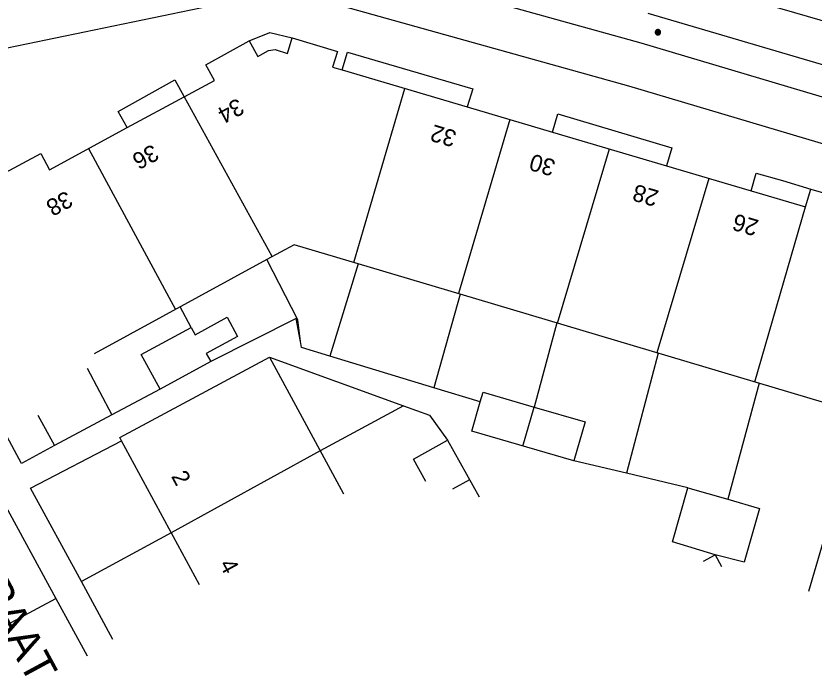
# Model space of a CAD drawing. Extents: x 81065 to 81486, y 452384 to 452681.
# Drawn here: x 81293.93 to 81331.82, y 452479.86 to 452511.24 of the extents above; entities that cross this region are included whole.
import ezdxf

# ---------------------------------------------------------------- set-up
doc = ezdxf.new("R2010")
doc.units = 0
for name, color, linetype in [('B-BH-AL-TOPOGRAFIE_HUISNUMMER-T25', 7, 'Continuous'), ('B-BH-AL-TOPOGRAFIE_STRAATNAAM-S', 7, 'Continuous'), ('B-BH-GR-BOOM-S', 7, 'Continuous'), ('B-BH-OG-TERREIN_ERF-GV', 7, 'Continuous'), ('B-BH-OG-TOPOGRAFIE_BEBOUWING-GV', 7, 'Continuous'), ('B-BH-OG-TOPOGRAFIE_BEBOUWING_PANDSCHEIDING-GV', 7, 'Continuous'), ('B-BH-VH-KANTOPSLUITING-GV', 7, 'Continuous')]:
    doc.layers.add(name, color=color, linetype=linetype)

msp = doc.modelspace()

# ---------------------------------------------------------------- linework, layer by layer
at = {"layer": 'B-BH-GR-BOOM-S'}
for points in [[(81324.281, 452510.463), (81324.282, 452510.449), (81324.284, 452510.436), (81324.288, 452510.423), (81324.292, 452510.41), (81324.299, 452510.398), (81324.306, 452510.387), (81324.314, 452510.377), (81324.324, 452510.367), (81324.334, 452510.359), (81324.346, 452510.351), (81324.358, 452510.345), (81324.37, 452510.34), (81324.383, 452510.337), (81324.397, 452510.335), (81324.41, 452510.334), (81324.424, 452510.335), (81324.437, 452510.337), (81324.45, 452510.34), (81324.463, 452510.345), (81324.475, 452510.351), (81324.486, 452510.359), (81324.496, 452510.367), (81324.506, 452510.377), (81324.515, 452510.387), (81324.522, 452510.398), (81324.528, 452510.41), (81324.533, 452510.423), (81324.536, 452510.436), (81324.538, 452510.449), (81324.539, 452510.463), (81324.538, 452510.476), (81324.536, 452510.49), (81324.533, 452510.503), (81324.528, 452510.515), (81324.522, 452510.527), (81324.515, 452510.539), (81324.506, 452510.549), (81324.496, 452510.559), (81324.486, 452510.567), (81324.475, 452510.575), (81324.463, 452510.581), (81324.45, 452510.585), (81324.437, 452510.589), (81324.424, 452510.591), (81324.41, 452510.592), (81324.397, 452510.591), (81324.383, 452510.589), (81324.37, 452510.585), (81324.358, 452510.581), (81324.346, 452510.575), (81324.334, 452510.567), (81324.324, 452510.559), (81324.314, 452510.549), (81324.306, 452510.539), (81324.299, 452510.527), (81324.292, 452510.515), (81324.288, 452510.503), (81324.284, 452510.49), (81324.282, 452510.476), (81324.281, 452510.463)], [(81324.306, 452510.463), (81324.306, 452510.452), (81324.308, 452510.441), (81324.311, 452510.431), (81324.315, 452510.42), (81324.32, 452510.411), (81324.326, 452510.402), (81324.333, 452510.393), (81324.34, 452510.385), (81324.349, 452510.378), (81324.358, 452510.372), (81324.368, 452510.367), (81324.378, 452510.364), (81324.389, 452510.361), (81324.399, 452510.359), (81324.41, 452510.358), (81324.421, 452510.359), (81324.432, 452510.361), (81324.443, 452510.364), (81324.453, 452510.367), (81324.462, 452510.372), (81324.472, 452510.378), (81324.48, 452510.385), (81324.488, 452510.393), (81324.495, 452510.402), (81324.501, 452510.411), (81324.506, 452510.42), (81324.51, 452510.431), (81324.512, 452510.441), (81324.514, 452510.452), (81324.515, 452510.463), (81324.514, 452510.474), (81324.512, 452510.485), (81324.51, 452510.495), (81324.506, 452510.505), (81324.501, 452510.515), (81324.495, 452510.524), (81324.488, 452510.533), (81324.48, 452510.54), (81324.472, 452510.547), (81324.462, 452510.553), (81324.453, 452510.558), (81324.443, 452510.562), (81324.432, 452510.565), (81324.421, 452510.567), (81324.41, 452510.567), (81324.399, 452510.567), (81324.389, 452510.565), (81324.378, 452510.562), (81324.368, 452510.558), (81324.358, 452510.553), (81324.349, 452510.547), (81324.34, 452510.54), (81324.333, 452510.533), (81324.326, 452510.524), (81324.32, 452510.515), (81324.315, 452510.505), (81324.311, 452510.495), (81324.308, 452510.485), (81324.306, 452510.474), (81324.306, 452510.463)], [(81324.329, 452510.463), (81324.329, 452510.454), (81324.33, 452510.446), (81324.333, 452510.438), (81324.336, 452510.43), (81324.34, 452510.422), (81324.344, 452510.415), (81324.35, 452510.408), (81324.356, 452510.402), (81324.362, 452510.397), (81324.369, 452510.392), (81324.377, 452510.388), (81324.385, 452510.385), (81324.393, 452510.383), (81324.402, 452510.382), (81324.41, 452510.381), (81324.419, 452510.382), (81324.427, 452510.383), (81324.435, 452510.385), (81324.443, 452510.388), (81324.451, 452510.392), (81324.458, 452510.397), (81324.465, 452510.402), (81324.471, 452510.408), (81324.476, 452510.415), (81324.481, 452510.422), (81324.485, 452510.43), (81324.488, 452510.438), (81324.49, 452510.446), (81324.491, 452510.454), (81324.492, 452510.463), (81324.491, 452510.471), (81324.49, 452510.48), (81324.488, 452510.488), (81324.485, 452510.496), (81324.481, 452510.504), (81324.476, 452510.511), (81324.471, 452510.518), (81324.465, 452510.523), (81324.458, 452510.529), (81324.451, 452510.533), (81324.443, 452510.537), (81324.435, 452510.54), (81324.427, 452510.543), (81324.419, 452510.544), (81324.41, 452510.544), (81324.402, 452510.544), (81324.393, 452510.543), (81324.385, 452510.54), (81324.377, 452510.537), (81324.369, 452510.533), (81324.362, 452510.529), (81324.356, 452510.523), (81324.35, 452510.518), (81324.344, 452510.511), (81324.34, 452510.504), (81324.336, 452510.496), (81324.333, 452510.488), (81324.33, 452510.48), (81324.329, 452510.471), (81324.329, 452510.463)], [(81324.352, 452510.463), (81324.352, 452510.457), (81324.353, 452510.451), (81324.354, 452510.445), (81324.357, 452510.439), (81324.359, 452510.434), (81324.363, 452510.428), (81324.367, 452510.424), (81324.371, 452510.419), (81324.376, 452510.415), (81324.381, 452510.412), (81324.386, 452510.409), (81324.392, 452510.407), (81324.398, 452510.405), (81324.404, 452510.404), (81324.41, 452510.404), (81324.416, 452510.404), (81324.422, 452510.405), (81324.428, 452510.407), (81324.434, 452510.409), (81324.44, 452510.412), (81324.445, 452510.415), (81324.449, 452510.419), (81324.454, 452510.424), (81324.458, 452510.428), (81324.461, 452510.434), (81324.464, 452510.439), (81324.466, 452510.445), (81324.468, 452510.451), (81324.469, 452510.457), (81324.469, 452510.463), (81324.469, 452510.469), (81324.468, 452510.475), (81324.466, 452510.481), (81324.464, 452510.487), (81324.461, 452510.492), (81324.458, 452510.497), (81324.454, 452510.502), (81324.449, 452510.507), (81324.445, 452510.51), (81324.44, 452510.514), (81324.434, 452510.517), (81324.428, 452510.519), (81324.422, 452510.52), (81324.416, 452510.521), (81324.41, 452510.522), (81324.404, 452510.521), (81324.398, 452510.52), (81324.392, 452510.519), (81324.386, 452510.517), (81324.381, 452510.514), (81324.376, 452510.51), (81324.371, 452510.507), (81324.367, 452510.502), (81324.363, 452510.497), (81324.359, 452510.492), (81324.357, 452510.487), (81324.354, 452510.481), (81324.353, 452510.475), (81324.352, 452510.469), (81324.352, 452510.463)], [(81324.374, 452510.463), (81324.375, 452510.459), (81324.375, 452510.455), (81324.376, 452510.452), (81324.378, 452510.448), (81324.379, 452510.445), (81324.381, 452510.442), (81324.384, 452510.439), (81324.386, 452510.436), (81324.389, 452510.434), (81324.392, 452510.432), (81324.396, 452510.43), (81324.399, 452510.429), (81324.403, 452510.428), (81324.407, 452510.427), (81324.41, 452510.427), (81324.414, 452510.427), (81324.418, 452510.428), (81324.421, 452510.429), (81324.425, 452510.43), (81324.428, 452510.432), (81324.431, 452510.434), (81324.434, 452510.436), (81324.437, 452510.439), (81324.439, 452510.442), (81324.441, 452510.445), (81324.443, 452510.448), (81324.444, 452510.452), (81324.445, 452510.455), (81324.446, 452510.459), (81324.446, 452510.463), (81324.446, 452510.467), (81324.445, 452510.47), (81324.444, 452510.474), (81324.443, 452510.477), (81324.441, 452510.481), (81324.439, 452510.484), (81324.437, 452510.487), (81324.434, 452510.489), (81324.431, 452510.492), (81324.428, 452510.494), (81324.425, 452510.496), (81324.421, 452510.497), (81324.418, 452510.498), (81324.414, 452510.498), (81324.41, 452510.499), (81324.407, 452510.498), (81324.403, 452510.498), (81324.399, 452510.497), (81324.396, 452510.496), (81324.392, 452510.494), (81324.389, 452510.492), (81324.386, 452510.489), (81324.384, 452510.487), (81324.381, 452510.484), (81324.379, 452510.481), (81324.378, 452510.477), (81324.376, 452510.474), (81324.375, 452510.47), (81324.375, 452510.467), (81324.374, 452510.463)], [(81324.397, 452510.463), (81324.397, 452510.461), (81324.398, 452510.46), (81324.398, 452510.459), (81324.398, 452510.458), (81324.399, 452510.456), (81324.4, 452510.455), (81324.401, 452510.454), (81324.402, 452510.453), (81324.403, 452510.452), (81324.404, 452510.452), (81324.405, 452510.451), (81324.406, 452510.451), (81324.408, 452510.45), (81324.409, 452510.45), (81324.41, 452510.45), (81324.412, 452510.45), (81324.413, 452510.45), (81324.414, 452510.451), (81324.415, 452510.451), (81324.417, 452510.452), (81324.418, 452510.452), (81324.419, 452510.453), (81324.42, 452510.454), (81324.421, 452510.455), (81324.421, 452510.456), (81324.422, 452510.458), (81324.423, 452510.459), (81324.423, 452510.46), (81324.423, 452510.461), (81324.423, 452510.463), (81324.423, 452510.464), (81324.423, 452510.466), (81324.423, 452510.467), (81324.422, 452510.468), (81324.421, 452510.469), (81324.421, 452510.471), (81324.42, 452510.471), (81324.419, 452510.472), (81324.418, 452510.473), (81324.417, 452510.474), (81324.415, 452510.475), (81324.414, 452510.475), (81324.413, 452510.476), (81324.412, 452510.476), (81324.41, 452510.476), (81324.409, 452510.476), (81324.408, 452510.476), (81324.406, 452510.475), (81324.405, 452510.475), (81324.404, 452510.474), (81324.403, 452510.473), (81324.402, 452510.472), (81324.401, 452510.471), (81324.4, 452510.471), (81324.399, 452510.469), (81324.398, 452510.468), (81324.398, 452510.467), (81324.398, 452510.466), (81324.397, 452510.464), (81324.397, 452510.463)]]:
    msp.add_lwpolyline(points, dxfattribs=at)
at = {"layer": 'B-BH-OG-TERREIN_ERF-GV'}
for p, q in [((81310.179, 452499.459), (81308.835, 452495.072)), ((81315.022, 452498.014), (81313.775, 452493.566)), ((81302.241, 452496.437), (81301.716, 452497.41)), ((81319.612, 452496.645), (81318.53, 452492.651)), ((81324.427, 452495.209), (81322.911, 452489.5)), ((81297.305, 452494.492), (81298.486, 452492.279)), ((81329.223, 452493.779), (81327.725, 452488.266)), ((81312.336, 452492.708), (81308.379, 452490.562)), ((81301.302, 452486.677), (81297.035, 452484.354))]:
    msp.add_line(p, q, dxfattribs=at)
msp.add_lwpolyline([(81307.43, 452495.761), (81307.306, 452496.79), (81305.843, 452499.661)], dxfattribs=at)
at = {"layer": 'B-BH-OG-TOPOGRAFIE_BEBOUWING-GV'}
for p, q in [((81309.422, 452508.675), (81315.358, 452506.916)), ((81299.207, 452505.932), (81301.913, 452507.4)), ((81315.358, 452506.916), (81319.411, 452505.716)), ((81319.411, 452505.716), (81324.811, 452504.117)), ((81324.811, 452504.117), (81328.838, 452502.923)), ((81331.67, 452503.013), (81336.689, 452501.516)), ((81303.178, 452494.808), (81300.775, 452493.495)), ((81305.973, 452495.015), (81309.477, 452488.531)), ((81314.416, 452491.075), (81315.92, 452488.38)), ((81325.836, 452488.803), (81327.725, 452488.266)), ((81327.133, 452485.628), (81327.437, 452485.072))]:
    msp.add_line(p, q, dxfattribs=at)
for points in [[(81301.913, 452507.4), (81303.346, 452508.178), (81302.936, 452508.923), (81305.007, 452510.063)], [(81305.007, 452510.063), (81305.417, 452509.318), (81305.919, 452509.595), (81306.231, 452509.649), (81306.82, 452509.458), (81307.043, 452510.206)], [(81307.043, 452510.206), (81309.193, 452509.557), (81308.964, 452508.811), (81309.422, 452508.675)], [(81295.749, 452490.824), (81294.191, 452489.974), (81292.702, 452492.703), (81292.52, 452492.606), (81289.503, 452498.156), (81288.453, 452500.086), (81290.406, 452501.174), (81289.998, 452501.96), (81295.103, 452504.706), (81295.52, 452503.931), (81299.207, 452505.932)], [(81328.838, 452502.923), (81331.416, 452502.16), (81331.67, 452503.013)], [(81334.029, 452492.346), (81315.022, 452498.014), (81310.179, 452499.459), (81307.134, 452500.366), (81305.843, 452499.661), (81297.632, 452495.182)], [(81302.241, 452496.437), (81302.431, 452496.089), (81303.952, 452496.92), (81304.45, 452496.009), (81302.964, 452495.198), (81303.178, 452494.808)], [(81300.775, 452493.495), (81299.874, 452495.145), (81302.241, 452496.437)], [(81298.933, 452491.052), (81298.851, 452491.204), (81305.973, 452495.015)], [(81315.977, 452492.895), (81316.109, 452493.351), (81318.53, 452492.651)], [(81320.412, 452490.096), (81315.572, 452491.496), (81315.977, 452492.895)], [(81318.53, 452492.651), (81320.949, 452491.951), (81320.412, 452490.096)], [(81294.964, 452492.264), (81295.749, 452490.824)], [(81302.641, 452484.203), (81298.933, 452491.052)], [(81313.393, 452489.106), (81312.798, 452490.172), (81314.416, 452491.075)], [(81327.133, 452485.628), (81325.108, 452486.245), (81325.836, 452488.803)], [(81327.725, 452488.266), (81329.241, 452487.835), (81328.514, 452485.276), (81327.133, 452485.628)], [(81326.572, 452485.321), (81327.133, 452485.628)]]:
    msp.add_lwpolyline(points, dxfattribs=at)
at = {"layer": 'B-BH-OG-TOPOGRAFIE_BEBOUWING_PANDSCHEIDING-GV'}
for p, q in [((81309.966, 452499.522), (81312.39, 452507.795)), ((81306.09, 452499.8), (81301.91, 452507.405)), ((81317.384, 452506.316), (81314.935, 452498.04)), ((81297.364, 452504.931), (81301.5, 452497.29)), ((81319.646, 452496.635), (81322.111, 452504.916)), ((81326.824, 452503.519), (81324.36, 452495.229)), ((81329.016, 452493.842), (81331.416, 452502.161)), ((81317.993, 452490.796), (81318.53, 452492.651)), ((81308.379, 452490.562), (81301.302, 452486.677)), ((81315.468, 452489.19), (81314.663, 452488.741))]:
    msp.add_line(p, q, dxfattribs=at)
at = {"layer": 'B-BH-VH-KANTOPSLUITING-GV'}
for p, q in [((81323.617, 452509.943), (81309.331, 452513.927)), ((81348.596, 452506.196), (81324.541, 452513.255)), ((81291.488, 452509.315), (81303.606, 452511.817)), ((81323.025, 452507.908), (81308.846, 452511.862)), ((81348.008, 452504.29), (81323.953, 452511.349)), ((81305.973, 452495.015), (81312.336, 452492.708)), ((81313.775, 452493.566), (81308.835, 452495.072)), ((81300.775, 452493.495), (81298.486, 452492.279)), ((81315.977, 452492.895), (81313.775, 452493.566)), ((81298.486, 452492.279), (81295.749, 452490.824)), ((81334.029, 452492.346), (81331.561, 452483.888)), ((81294.616, 452488.797), (81298.933, 452491.052)), ((81322.911, 452489.5), (81320.412, 452490.096)), ((81325.836, 452488.803), (81322.911, 452489.5)), ((81297.035, 452484.354), (81294.616, 452488.797)), ((81293.235, 452488.298), (81295.818, 452483.556)), ((81298.533, 452481.602), (81297.035, 452484.354)), ((81291.371, 452481.154), (81295.818, 452483.556)), ((81295.818, 452483.556), (81297.306, 452480.825))]:
    msp.add_line(p, q, dxfattribs=at)
for points in [[(81305.007, 452510.063), (81305.983, 452510.46), (81307.043, 452510.206)], [(81347.493, 452502.83), (81323.617, 452509.943)], [(81309.422, 452508.675), (81309.677, 452509.512), (81315.624, 452507.782), (81315.358, 452506.916)], [(81299.207, 452505.932), (81298.779, 452506.695), (81301.464, 452508.2), (81301.913, 452507.4)], [(81346.914, 452500.791), (81323.025, 452507.908)], [(81319.411, 452505.716), (81319.653, 452506.592), (81325.067, 452504.977), (81324.811, 452504.117)], [(81328.838, 452502.923), (81329.078, 452503.774), (81330.333, 452503.42), (81331.67, 452503.013)], [(81307.43, 452495.761), (81307.229, 452496.862), (81303.178, 452494.808)], [(81308.835, 452495.072), (81307.48, 452495.484), (81307.43, 452495.761)], [(81312.336, 452492.708), (81313.567, 452492.262), (81314.416, 452491.075)]]:
    msp.add_lwpolyline(points, dxfattribs=at)

# ---------------------------------------------------------------- texts
at = {"layer": 'B-BH-AL-TOPOGRAFIE_HUISNUMMER-T25'}
for s, rotation, p in [('34', 208.4161, (81304.468, 452507.361)), ('32', 163.5535, (81314.905, 452505.753)), ('36', 208.4161, (81300.419, 452505.171)), ('30', 163.5535, (81319.604, 452504.367)), ('28', 163.5535, (81324.504, 452502.92)), ('38', 208.4161, (81296.325, 452502.956)), ('26', 163.5535, (81329.248, 452501.52)), ('2', 298.5667, (81301.278, 452489.36)), ('4', 298.5667, (81303.56, 452485.169))]:
    msp.add_text(s, height=0.8, rotation=rotation, dxfattribs=at).set_placement(p)
at = {"layer": 'B-BH-AL-TOPOGRAFIE_STRAATNAAM-S'}
for s, rotation, p in [('HILDEBRANDSTRAAT', 343.4847, (81322.062, 452514.938)), ('STASTOKSTRAAT', 298.4741, (81286.385, 452494.592))]:
    msp.add_text(s, height=1.5, rotation=rotation, dxfattribs=at).set_placement(p)

doc.saveas('drawing.dxf')
